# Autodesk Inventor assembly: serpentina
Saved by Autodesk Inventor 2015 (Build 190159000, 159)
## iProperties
Created: 2015-06
Part Number: serpentina
Document SubType Name: Assembly
Designer: Franzi-CAD
Translation Standard: IGES 5.3
FileName: 1 Sistema de RefrigeraÃ§Ã£o Industrial - 3D v3
PreProcessor: AutoCAD 2015 - English
PostProcessor: Build: 160, Release: 2012 RTM - Date: Tue 03/01/2011
Sent Units: millimeter
Uncertainty: 0.01
Author: Franzi-CAD
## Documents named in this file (3)
- C:\Users\Renato\Desktop\Refrigeração\serpentina.iam
- C:\Users\Renato\Desktop\Refrigeração\expansÃ£o.ipt
- C:\Users\Renato\Desktop\Refrigeração\serpentina.ipt
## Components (3 placed, 2 different names)
1. expansÃ£o:1
2. expansÃ£o:2
3. serpentina:1
